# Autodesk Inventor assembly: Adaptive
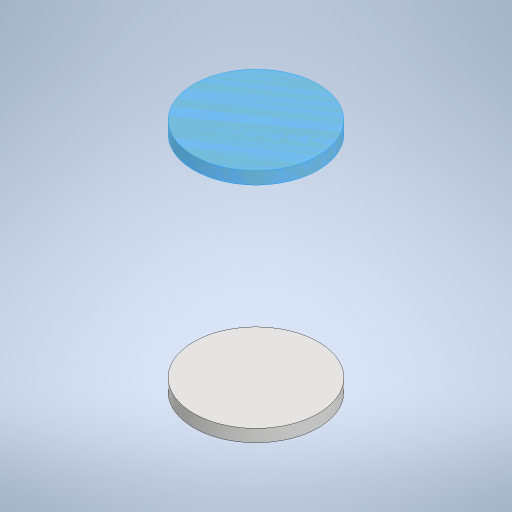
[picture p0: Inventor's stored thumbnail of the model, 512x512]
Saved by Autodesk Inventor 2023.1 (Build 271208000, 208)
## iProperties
Created: 2022-08
Part Number: Adaptive
Document SubType Name: Assembly
Designer: milos
Author: milos
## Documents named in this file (3)
- C:\Users\milos\Desktop\Adaptive.iam
- C:\Users\milos\Documents\Inventor\Enigma\Parts\Base.ipt
- C:\Users\milos\Documents\Inventor\Enigma\Adaptive.ipt
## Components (3 placed, 2 different names)
1. Base:1 — Mate:1
2. Base:2 — Mate:1
3. Adaptive:1
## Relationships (1: Mate 1)
- Mate:1: Base:1 ↔ Base:2
